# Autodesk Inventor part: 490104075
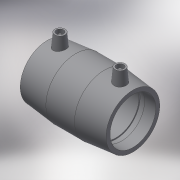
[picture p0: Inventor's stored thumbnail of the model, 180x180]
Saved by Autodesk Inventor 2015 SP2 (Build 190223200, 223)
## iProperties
Created: 2017-06
Part Number: 490104075
Material: Generic
Description: PLASSON COUPLER 75-75
Document SubType Name: Modeling
Designer: KIM
Mass: 335.804 g
Surface Area: 753.337 cm^2
Volume: 335.804 cm^3
Density: 1 g/cm^3
Appearance: Default
Author: KIM
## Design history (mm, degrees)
derived "490104.ipt"
feature "Solid1::490104.ipt"
tag "TaggingFeature1"
body "Solid1"
other parameters: "d0" = 126, "d1" = 75, "d2" = 98, "d3" = 61, "d4" = 42, "d5" = 88.2, "d6" = 71.25, "d7" = 75, "d8" = 168 deg, "d10" = 24.4, "d11" = 8.13333, "d13" = 126, "d14" = 17.6296, "d15" = 61, "d16" = 61, "d17" = 71.25, "d18" = 75, "d19" = 3.52592, "d20" = 168 deg, "d22" = 92.12, "d23" = 98, "d24" = 89.3564, "d25" = 135 deg, "d26" = 50.4, "d27" = 135 deg, "d29" = 64, "d30" = 14, "d31" = 44.1, "d34" = 5 deg, "d35" = 15, "d39" = 5 deg, "d41" = 4, "d42" = 14, "d43" = 0, "d45" = 4, "d46" = 14, "d47" = 0, "d48" = 3, "d49" = 0, "d50" = 3, "d51" = 0, "d52" = 17.69, "d53" = 4.4225, "d_" = 75, "L_" = 126, "L_1" = 61, "D_" = 98, "A_" = 64, "d_2" = 12
